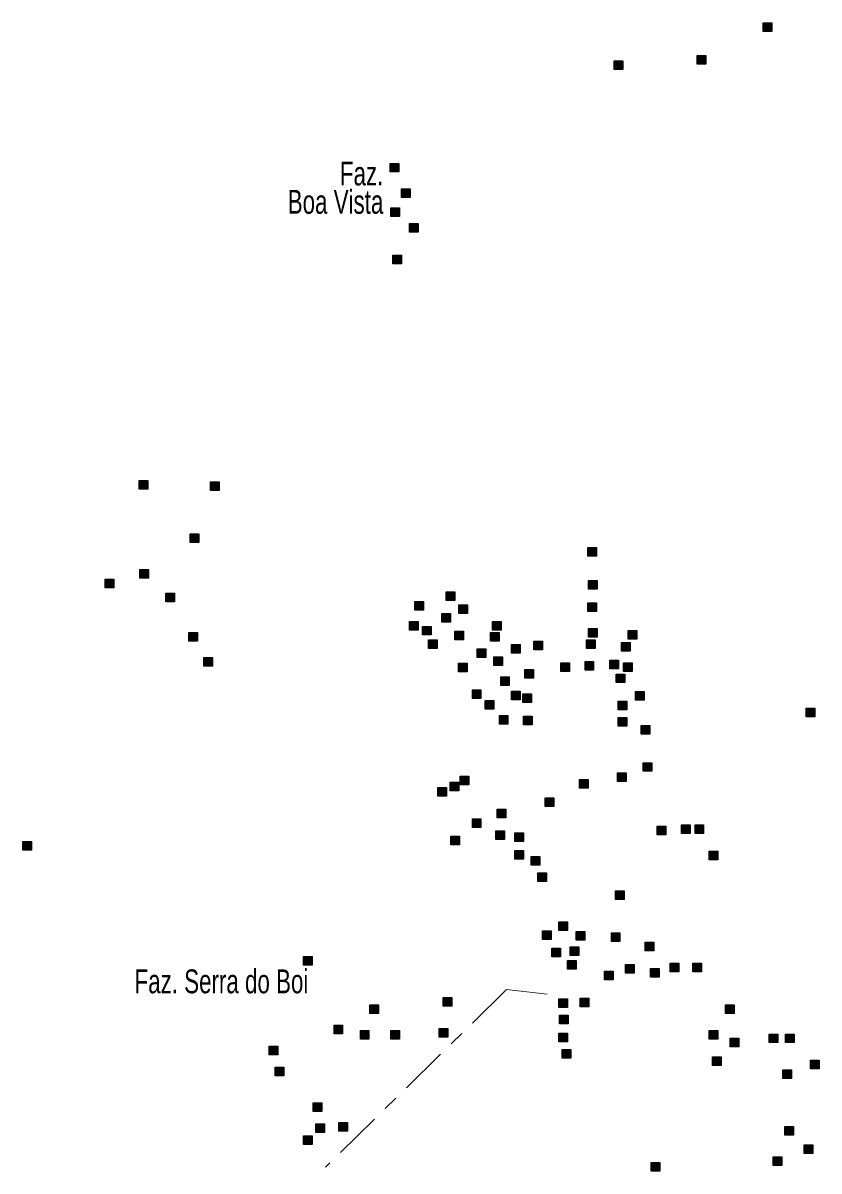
# Model space of a CAD drawing. Extents: x 445.4 to 500, y 8728.7 to 8784.
# Drawn here: x 457.46 to 462.8, y 8764.49 to 8772.19 of the extents above; entities that cross this region are included whole.
import ezdxf
from ezdxf.enums import TextEntityAlignment as Align

# ---------------------------------------------------------------- set-up
doc = ezdxf.new("R2010")
doc.units = 0
doc.header["$LTSCALE"] = 0.064
doc.linetypes.add('DOT_DASHED', pattern=[7.7, 5, -1.2, 0.3, -1.2])
doc.layers.add('2', color=7, linetype='Continuous', lineweight=25)
doc.layers.add('22', color=7, linetype='DOT_DASHED', lineweight=13)
doc.layers.add('61', color=7, linetype='Continuous')

msp = doc.modelspace()

# ---------------------------------------------------------------- hatches: boundary and pattern name
at = {"layer": '2'}
for points in [[(462.4248, 8772.1869), (462.4828, 8772.1869), (462.4828, 8772.1289), (462.4248, 8772.1289)], [(461.9814, 8771.9696), (462.0394, 8771.9696), (462.0394, 8771.9116), (461.9814, 8771.9116)], [(461.4248, 8771.9334), (461.4828, 8771.9334), (461.4828, 8771.8754), (461.4248, 8771.8754)], [(459.9225, 8771.2452), (459.9805, 8771.2452), (459.9805, 8771.1872), (459.9225, 8771.1872)], [(459.9994, 8771.0732), (460.0574, 8771.0732), (460.0574, 8771.0152), (459.9994, 8771.0152)], [(459.927, 8770.9464), (459.985, 8770.9464), (459.985, 8770.8884), (459.927, 8770.8884)], [(460.0537, 8770.8423), (460.1117, 8770.8423), (460.1117, 8770.7843), (460.0537, 8770.7843)], [(459.9406, 8770.6295), (459.9986, 8770.6295), (459.9986, 8770.5715), (459.9406, 8770.5715)], [(458.2392, 8769.1173), (458.2972, 8769.1173), (458.2972, 8769.0593), (458.2392, 8769.0593)], [(458.7188, 8769.1083), (458.7768, 8769.1083), (458.7768, 8769.0503), (458.7188, 8769.0503)], [(458.5831, 8768.7597), (458.6411, 8768.7597), (458.6411, 8768.7017), (458.5831, 8768.7017)], [(461.2483, 8768.6691), (461.3063, 8768.6691), (461.3063, 8768.6111), (461.2483, 8768.6111)], [(458.2437, 8768.5197), (458.3017, 8768.5197), (458.3017, 8768.4617), (458.2437, 8768.4617)], [(458.0129, 8768.4563), (458.0709, 8768.4563), (458.0709, 8768.3983), (458.0129, 8768.3983)], [(461.2529, 8768.4473), (461.3109, 8768.4473), (461.3109, 8768.3893), (461.2529, 8768.3893)], [(458.42, 8768.3613), (458.478, 8768.3613), (458.478, 8768.3033), (458.42, 8768.3033)], [(460.2981, 8768.3703), (460.3561, 8768.3703), (460.3561, 8768.3123), (460.2981, 8768.3123)], [(460.0899, 8768.3069), (460.1479, 8768.3069), (460.1479, 8768.2489), (460.0899, 8768.2489)], [(460.3841, 8768.2843), (460.4421, 8768.2843), (460.4421, 8768.2263), (460.3841, 8768.2263)], [(461.2483, 8768.2979), (461.3063, 8768.2979), (461.3063, 8768.2399), (461.2483, 8768.2399)], [(460.0537, 8768.1711), (460.1117, 8768.1711), (460.1117, 8768.1131), (460.0537, 8768.1131)], [(460.2709, 8768.2254), (460.3289, 8768.2254), (460.3289, 8768.1674), (460.2709, 8768.1674)], [(460.6103, 8768.1711), (460.6683, 8768.1711), (460.6683, 8768.1131), (460.6103, 8768.1131)], [(458.574, 8768.0987), (458.632, 8768.0987), (458.632, 8768.0407), (458.574, 8768.0407)], [(460.1397, 8768.1394), (460.1977, 8768.1394), (460.1977, 8768.0814), (460.1397, 8768.0814)], [(460.3569, 8768.1077), (460.4149, 8768.1077), (460.4149, 8768.0497), (460.3569, 8768.0497)], [(460.5967, 8768.0987), (460.6547, 8768.0987), (460.6547, 8768.0407), (460.5967, 8768.0407)], [(461.2529, 8768.1258), (461.3109, 8768.1258), (461.3109, 8768.0678), (461.2529, 8768.0678)], [(461.5198, 8768.1122), (461.5778, 8768.1122), (461.5778, 8768.0542), (461.5198, 8768.0542)], [(460.1804, 8768.0489), (460.2384, 8768.0489), (460.2384, 8767.9909), (460.1804, 8767.9909)], [(460.737, 8768.0172), (460.795, 8768.0172), (460.795, 8767.9592), (460.737, 8767.9592)], [(460.8863, 8768.0398), (460.9443, 8768.0398), (460.9443, 8767.9818), (460.8863, 8767.9818)], [(461.2393, 8768.0489), (461.2973, 8768.0489), (461.2973, 8767.9909), (461.2393, 8767.9909)], [(461.4746, 8768.0308), (461.5326, 8768.0308), (461.5326, 8767.9728), (461.4746, 8767.9728)], [(458.6736, 8767.9311), (458.7316, 8767.9311), (458.7316, 8767.8731), (458.6736, 8767.8731)], [(460.5062, 8767.989), (460.5642, 8767.989), (460.5642, 8767.931), (460.5062, 8767.931)], [(460.6194, 8767.9347), (460.6774, 8767.9347), (460.6774, 8767.8767), (460.6194, 8767.8767)], [(460.3824, 8767.8916), (460.4404, 8767.8916), (460.4404, 8767.8336), (460.3824, 8767.8336)], [(461.0673, 8767.8949), (461.1253, 8767.8949), (461.1253, 8767.8369), (461.0673, 8767.8369)], [(461.2302, 8767.904), (461.2882, 8767.904), (461.2882, 8767.846), (461.2302, 8767.846)], [(461.3977, 8767.913), (461.4557, 8767.913), (461.4557, 8767.855), (461.3977, 8767.855)], [(461.4882, 8767.8949), (461.5462, 8767.8949), (461.5462, 8767.8369), (461.4882, 8767.8369)], [(460.6646, 8767.7999), (460.7226, 8767.7999), (460.7226, 8767.7419), (460.6646, 8767.7419)], [(460.8275, 8767.8497), (460.8855, 8767.8497), (460.8855, 8767.7917), (460.8275, 8767.7917)], [(461.4384, 8767.8197), (461.4964, 8767.8197), (461.4964, 8767.7617), (461.4384, 8767.7617)], [(460.4746, 8767.7138), (460.5326, 8767.7138), (460.5326, 8767.6558), (460.4746, 8767.6558)], [(460.737, 8767.7048), (460.795, 8767.7048), (460.795, 8767.6468), (460.737, 8767.6468)], [(461.5696, 8767.702), (461.6276, 8767.702), (461.6276, 8767.644), (461.5696, 8767.644)], [(460.5605, 8767.6414), (460.6185, 8767.6414), (460.6185, 8767.5834), (460.5605, 8767.5834)], [(460.8139, 8767.6867), (460.8719, 8767.6867), (460.8719, 8767.6287), (460.8139, 8767.6287)], [(461.452, 8767.6369), (461.51, 8767.6369), (461.51, 8767.5789), (461.452, 8767.5789)], [(462.7139, 8767.5903), (462.7719, 8767.5903), (462.7719, 8767.5323), (462.7139, 8767.5323)], [(460.6556, 8767.5418), (460.7136, 8767.5418), (460.7136, 8767.4838), (460.6556, 8767.4838)], [(460.8185, 8767.5373), (460.8765, 8767.5373), (460.8765, 8767.4793), (460.8185, 8767.4793)], [(461.452, 8767.5282), (461.51, 8767.5282), (461.51, 8767.4702), (461.452, 8767.4702)], [(461.6058, 8767.4739), (461.6638, 8767.4739), (461.6638, 8767.4159), (461.6058, 8767.4159)], [(461.6194, 8767.2249), (461.6774, 8767.2249), (461.6774, 8767.1669), (461.6194, 8767.1669)], [(460.3252, 8767.0936), (460.3832, 8767.0936), (460.3832, 8767.0356), (460.3252, 8767.0356)], [(460.3931, 8767.1343), (460.4511, 8767.1343), (460.4511, 8767.0763), (460.3931, 8767.0763)], [(461.194, 8767.1117), (461.252, 8767.1117), (461.252, 8767.0537), (461.194, 8767.0537)], [(461.4474, 8767.157), (461.5054, 8767.157), (461.5054, 8767.099), (461.4474, 8767.099)], [(460.2438, 8767.0574), (460.3018, 8767.0574), (460.3018, 8766.9994), (460.2438, 8766.9994)], [(460.9633, 8766.9894), (461.0213, 8766.9894), (461.0213, 8766.9314), (460.9633, 8766.9314)], [(460.642, 8766.9125), (460.7, 8766.9125), (460.7, 8766.8545), (460.642, 8766.8545)], [(460.4746, 8766.8491), (460.5326, 8766.8491), (460.5326, 8766.7911), (460.4746, 8766.7911)], [(461.7144, 8766.7993), (461.7724, 8766.7993), (461.7724, 8766.7413), (461.7144, 8766.7413)], [(461.8773, 8766.8083), (461.9353, 8766.8083), (461.9353, 8766.7503), (461.8773, 8766.7503)], [(461.9678, 8766.8083), (462.0258, 8766.8083), (462.0258, 8766.7503), (461.9678, 8766.7503)], [(460.3298, 8766.7314), (460.3878, 8766.7314), (460.3878, 8766.6734), (460.3298, 8766.6734)], [(460.6329, 8766.7676), (460.6909, 8766.7676), (460.6909, 8766.7096), (460.6329, 8766.7096)], [(460.7596, 8766.754), (460.8176, 8766.754), (460.8176, 8766.696), (460.7596, 8766.696)], [(457.4609, 8766.6952), (457.5189, 8766.6952), (457.5189, 8766.6372), (457.4609, 8766.6372)], [(460.7596, 8766.6363), (460.8176, 8766.6363), (460.8176, 8766.5783), (460.7596, 8766.5783)], [(462.0628, 8766.6318), (462.1208, 8766.6318), (462.1208, 8766.5738), (462.0628, 8766.5738)], [(460.8682, 8766.5956), (460.9262, 8766.5956), (460.9262, 8766.5376), (460.8682, 8766.5376)], [(460.9135, 8766.4869), (460.9715, 8766.4869), (460.9715, 8766.4289), (460.9135, 8766.4289)], [(461.4339, 8766.3647), (461.4919, 8766.3647), (461.4919, 8766.3067), (461.4339, 8766.3067)], [(460.9452, 8766.0975), (461.0032, 8766.0975), (461.0032, 8766.0395), (460.9452, 8766.0395)], [(461.0538, 8766.1564), (461.1118, 8766.1564), (461.1118, 8766.0984), (461.0538, 8766.0984)], [(461.1714, 8766.093), (461.2294, 8766.093), (461.2294, 8766.035), (461.1714, 8766.035)], [(461.4067, 8766.084), (461.4647, 8766.084), (461.4647, 8766.026), (461.4067, 8766.026)], [(461.633, 8766.0206), (461.691, 8766.0206), (461.691, 8765.9626), (461.633, 8765.9626)], [(461.0085, 8765.9798), (461.0665, 8765.9798), (461.0665, 8765.9218), (461.0085, 8765.9218)], [(461.1307, 8765.9889), (461.1887, 8765.9889), (461.1887, 8765.9309), (461.1307, 8765.9309)], [(459.3433, 8765.9255), (459.4013, 8765.9255), (459.4013, 8765.8675), (459.3433, 8765.8675)], [(461.1126, 8765.8983), (461.1706, 8765.8983), (461.1706, 8765.8403), (461.1126, 8765.8403)], [(461.5017, 8765.8712), (461.5597, 8765.8712), (461.5597, 8765.8132), (461.5017, 8765.8132)], [(461.8004, 8765.8802), (461.8584, 8765.8802), (461.8584, 8765.8222), (461.8004, 8765.8222)], [(461.9542, 8765.8802), (462.0122, 8765.8802), (462.0122, 8765.8222), (461.9542, 8765.8222)], [(461.3615, 8765.8259), (461.4195, 8765.8259), (461.4195, 8765.7679), (461.3615, 8765.7679)], [(461.6692, 8765.844), (461.7272, 8765.844), (461.7272, 8765.786), (461.6692, 8765.786)], [(460.28, 8765.6493), (460.338, 8765.6493), (460.338, 8765.5913), (460.28, 8765.5913)], [(461.0538, 8765.6403), (461.1118, 8765.6403), (461.1118, 8765.5823), (461.0538, 8765.5823)], [(461.1986, 8765.6448), (461.2566, 8765.6448), (461.2566, 8765.5868), (461.1986, 8765.5868)], [(459.7867, 8765.5995), (459.8447, 8765.5995), (459.8447, 8765.5415), (459.7867, 8765.5415)], [(462.1714, 8765.5995), (462.2294, 8765.5995), (462.2294, 8765.5415), (462.1714, 8765.5415)], [(461.0583, 8765.5316), (461.1163, 8765.5316), (461.1163, 8765.4736), (461.0583, 8765.4736)], [(459.5469, 8765.4637), (459.6049, 8765.4637), (459.6049, 8765.4057), (459.5469, 8765.4057)], [(459.7234, 8765.4275), (459.7814, 8765.4275), (459.7814, 8765.3695), (459.7234, 8765.3695)], [(459.927, 8765.4275), (459.985, 8765.4275), (459.985, 8765.3695), (459.927, 8765.3695)], [(460.2528, 8765.4411), (460.3108, 8765.4411), (460.3108, 8765.3831), (460.2528, 8765.3831)], [(461.0538, 8765.4094), (461.1118, 8765.4094), (461.1118, 8765.3514), (461.0538, 8765.3514)], [(462.0628, 8765.4275), (462.1208, 8765.4275), (462.1208, 8765.3695), (462.0628, 8765.3695)], [(462.4656, 8765.4048), (462.5236, 8765.4048), (462.5236, 8765.3468), (462.4656, 8765.3468)], [(462.5742, 8765.4048), (462.6322, 8765.4048), (462.6322, 8765.3468), (462.5742, 8765.3468)], [(459.1125, 8765.3233), (459.1705, 8765.3233), (459.1705, 8765.2653), (459.1125, 8765.2653)], [(462.2031, 8765.3777), (462.2611, 8765.3777), (462.2611, 8765.3197), (462.2031, 8765.3197)], [(461.0764, 8765.3007), (461.1344, 8765.3007), (461.1344, 8765.2427), (461.0764, 8765.2427)], [(462.0855, 8765.2509), (462.1435, 8765.2509), (462.1435, 8765.1929), (462.0855, 8765.1929)], [(459.1532, 8765.183), (459.2112, 8765.183), (459.2112, 8765.125), (459.1532, 8765.125)], [(462.5561, 8765.1649), (462.6141, 8765.1649), (462.6141, 8765.1069), (462.5561, 8765.1069)], [(462.7416, 8765.2283), (462.7996, 8765.2283), (462.7996, 8765.1703), (462.7416, 8765.1703)], [(459.4066, 8764.943), (459.4646, 8764.943), (459.4646, 8764.885), (459.4066, 8764.885)], [(459.4247, 8764.8027), (459.4827, 8764.8027), (459.4827, 8764.7447), (459.4247, 8764.7447)], [(459.5786, 8764.8117), (459.6366, 8764.8117), (459.6366, 8764.7537), (459.5786, 8764.7537)], [(462.5696, 8764.7846), (462.6276, 8764.7846), (462.6276, 8764.7266), (462.5696, 8764.7266)], [(459.3433, 8764.7212), (459.4013, 8764.7212), (459.4013, 8764.6632), (459.3433, 8764.6632)], [(462.7009, 8764.6613), (462.7589, 8764.6613), (462.7589, 8764.6033), (462.7009, 8764.6033)], [(461.6737, 8764.5436), (461.7317, 8764.5436), (461.7317, 8764.4856), (461.6737, 8764.4856)], [(462.4927, 8764.5799), (462.5507, 8764.5799), (462.5507, 8764.5219), (462.4927, 8764.5219)]]:
    msp.add_hatch(color=256, dxfattribs=at).paths.add_polyline_path(points)

# ---------------------------------------------------------------- linework, layer by layer
for points in [[(462.4248, 8772.1869), (462.4828, 8772.1869), (462.4828, 8772.1289), (462.4248, 8772.1289)], [(461.9814, 8771.9696), (462.0394, 8771.9696), (462.0394, 8771.9116), (461.9814, 8771.9116)], [(461.4248, 8771.9334), (461.4828, 8771.9334), (461.4828, 8771.8754), (461.4248, 8771.8754)], [(459.9225, 8771.2452), (459.9805, 8771.2452), (459.9805, 8771.1872), (459.9225, 8771.1872)], [(459.9994, 8771.0732), (460.0574, 8771.0732), (460.0574, 8771.0152), (459.9994, 8771.0152)], [(459.927, 8770.9464), (459.985, 8770.9464), (459.985, 8770.8884), (459.927, 8770.8884)], [(460.0537, 8770.8423), (460.1117, 8770.8423), (460.1117, 8770.7843), (460.0537, 8770.7843)], [(459.9406, 8770.6295), (459.9986, 8770.6295), (459.9986, 8770.5715), (459.9406, 8770.5715)], [(458.2392, 8769.1173), (458.2972, 8769.1173), (458.2972, 8769.0593), (458.2392, 8769.0593)], [(458.7188, 8769.1083), (458.7768, 8769.1083), (458.7768, 8769.0503), (458.7188, 8769.0503)], [(458.5831, 8768.7597), (458.6411, 8768.7597), (458.6411, 8768.7017), (458.5831, 8768.7017)], [(461.2483, 8768.6691), (461.3063, 8768.6691), (461.3063, 8768.6111), (461.2483, 8768.6111)], [(458.2437, 8768.5197), (458.3017, 8768.5197), (458.3017, 8768.4617), (458.2437, 8768.4617)], [(458.0129, 8768.4563), (458.0709, 8768.4563), (458.0709, 8768.3983), (458.0129, 8768.3983)], [(461.2529, 8768.4473), (461.3109, 8768.4473), (461.3109, 8768.3893), (461.2529, 8768.3893)], [(458.42, 8768.3613), (458.478, 8768.3613), (458.478, 8768.3033), (458.42, 8768.3033)], [(460.2981, 8768.3703), (460.3561, 8768.3703), (460.3561, 8768.3123), (460.2981, 8768.3123)], [(460.0899, 8768.3069), (460.1479, 8768.3069), (460.1479, 8768.2489), (460.0899, 8768.2489)], [(460.3841, 8768.2843), (460.4421, 8768.2843), (460.4421, 8768.2263), (460.3841, 8768.2263)], [(461.2483, 8768.2979), (461.3063, 8768.2979), (461.3063, 8768.2399), (461.2483, 8768.2399)], [(460.0537, 8768.1711), (460.1117, 8768.1711), (460.1117, 8768.1131), (460.0537, 8768.1131)], [(460.2709, 8768.2254), (460.3289, 8768.2254), (460.3289, 8768.1674), (460.2709, 8768.1674)], [(460.6103, 8768.1711), (460.6683, 8768.1711), (460.6683, 8768.1131), (460.6103, 8768.1131)], [(458.574, 8768.0987), (458.632, 8768.0987), (458.632, 8768.0407), (458.574, 8768.0407)], [(460.1397, 8768.1394), (460.1977, 8768.1394), (460.1977, 8768.0814), (460.1397, 8768.0814)], [(460.3569, 8768.1077), (460.4149, 8768.1077), (460.4149, 8768.0497), (460.3569, 8768.0497)], [(460.5967, 8768.0987), (460.6547, 8768.0987), (460.6547, 8768.0407), (460.5967, 8768.0407)], [(461.2529, 8768.1258), (461.3109, 8768.1258), (461.3109, 8768.0678), (461.2529, 8768.0678)], [(461.5198, 8768.1122), (461.5778, 8768.1122), (461.5778, 8768.0542), (461.5198, 8768.0542)], [(460.1804, 8768.0489), (460.2384, 8768.0489), (460.2384, 8767.9909), (460.1804, 8767.9909)], [(460.737, 8768.0172), (460.795, 8768.0172), (460.795, 8767.9592), (460.737, 8767.9592)], [(460.8863, 8768.0398), (460.9443, 8768.0398), (460.9443, 8767.9818), (460.8863, 8767.9818)], [(461.2393, 8768.0489), (461.2973, 8768.0489), (461.2973, 8767.9909), (461.2393, 8767.9909)], [(461.4746, 8768.0308), (461.5326, 8768.0308), (461.5326, 8767.9728), (461.4746, 8767.9728)], [(458.6736, 8767.9311), (458.7316, 8767.9311), (458.7316, 8767.8731), (458.6736, 8767.8731)], [(460.5062, 8767.989), (460.5642, 8767.989), (460.5642, 8767.931), (460.5062, 8767.931)], [(460.6194, 8767.9347), (460.6774, 8767.9347), (460.6774, 8767.8767), (460.6194, 8767.8767)], [(460.3824, 8767.8916), (460.4404, 8767.8916), (460.4404, 8767.8336), (460.3824, 8767.8336)], [(461.0673, 8767.8949), (461.1253, 8767.8949), (461.1253, 8767.8369), (461.0673, 8767.8369)], [(461.2302, 8767.904), (461.2882, 8767.904), (461.2882, 8767.846), (461.2302, 8767.846)], [(461.3977, 8767.913), (461.4557, 8767.913), (461.4557, 8767.855), (461.3977, 8767.855)], [(461.4882, 8767.8949), (461.5462, 8767.8949), (461.5462, 8767.8369), (461.4882, 8767.8369)], [(460.6646, 8767.7999), (460.7226, 8767.7999), (460.7226, 8767.7419), (460.6646, 8767.7419)], [(460.8275, 8767.8497), (460.8855, 8767.8497), (460.8855, 8767.7917), (460.8275, 8767.7917)], [(461.4384, 8767.8197), (461.4964, 8767.8197), (461.4964, 8767.7617), (461.4384, 8767.7617)], [(460.4746, 8767.7138), (460.5326, 8767.7138), (460.5326, 8767.6558), (460.4746, 8767.6558)], [(460.737, 8767.7048), (460.795, 8767.7048), (460.795, 8767.6468), (460.737, 8767.6468)], [(461.5696, 8767.702), (461.6276, 8767.702), (461.6276, 8767.644), (461.5696, 8767.644)], [(460.5605, 8767.6414), (460.6185, 8767.6414), (460.6185, 8767.5834), (460.5605, 8767.5834)], [(460.8139, 8767.6867), (460.8719, 8767.6867), (460.8719, 8767.6287), (460.8139, 8767.6287)], [(461.452, 8767.6369), (461.51, 8767.6369), (461.51, 8767.5789), (461.452, 8767.5789)], [(462.7139, 8767.5903), (462.7719, 8767.5903), (462.7719, 8767.5323), (462.7139, 8767.5323)], [(460.6556, 8767.5418), (460.7136, 8767.5418), (460.7136, 8767.4838), (460.6556, 8767.4838)], [(460.8185, 8767.5373), (460.8765, 8767.5373), (460.8765, 8767.4793), (460.8185, 8767.4793)], [(461.452, 8767.5282), (461.51, 8767.5282), (461.51, 8767.4702), (461.452, 8767.4702)], [(461.6058, 8767.4739), (461.6638, 8767.4739), (461.6638, 8767.4159), (461.6058, 8767.4159)], [(461.6194, 8767.2249), (461.6774, 8767.2249), (461.6774, 8767.1669), (461.6194, 8767.1669)], [(460.3252, 8767.0936), (460.3832, 8767.0936), (460.3832, 8767.0356), (460.3252, 8767.0356)], [(460.3931, 8767.1343), (460.4511, 8767.1343), (460.4511, 8767.0763), (460.3931, 8767.0763)], [(461.194, 8767.1117), (461.252, 8767.1117), (461.252, 8767.0537), (461.194, 8767.0537)], [(461.4474, 8767.157), (461.5054, 8767.157), (461.5054, 8767.099), (461.4474, 8767.099)], [(460.2438, 8767.0574), (460.3018, 8767.0574), (460.3018, 8766.9994), (460.2438, 8766.9994)], [(460.9633, 8766.9894), (461.0213, 8766.9894), (461.0213, 8766.9314), (460.9633, 8766.9314)], [(460.642, 8766.9125), (460.7, 8766.9125), (460.7, 8766.8545), (460.642, 8766.8545)], [(460.4746, 8766.8491), (460.5326, 8766.8491), (460.5326, 8766.7911), (460.4746, 8766.7911)], [(461.7144, 8766.7993), (461.7724, 8766.7993), (461.7724, 8766.7413), (461.7144, 8766.7413)], [(461.8773, 8766.8083), (461.9353, 8766.8083), (461.9353, 8766.7503), (461.8773, 8766.7503)], [(461.9678, 8766.8083), (462.0258, 8766.8083), (462.0258, 8766.7503), (461.9678, 8766.7503)], [(460.3298, 8766.7314), (460.3878, 8766.7314), (460.3878, 8766.6734), (460.3298, 8766.6734)], [(460.6329, 8766.7676), (460.6909, 8766.7676), (460.6909, 8766.7096), (460.6329, 8766.7096)], [(460.7596, 8766.754), (460.8176, 8766.754), (460.8176, 8766.696), (460.7596, 8766.696)], [(457.4609, 8766.6952), (457.5189, 8766.6952), (457.5189, 8766.6372), (457.4609, 8766.6372)], [(460.7596, 8766.6363), (460.8176, 8766.6363), (460.8176, 8766.5783), (460.7596, 8766.5783)], [(462.0628, 8766.6318), (462.1208, 8766.6318), (462.1208, 8766.5738), (462.0628, 8766.5738)], [(460.8682, 8766.5956), (460.9262, 8766.5956), (460.9262, 8766.5376), (460.8682, 8766.5376)], [(460.9135, 8766.4869), (460.9715, 8766.4869), (460.9715, 8766.4289), (460.9135, 8766.4289)], [(461.4339, 8766.3647), (461.4919, 8766.3647), (461.4919, 8766.3067), (461.4339, 8766.3067)], [(460.9452, 8766.0975), (461.0032, 8766.0975), (461.0032, 8766.0395), (460.9452, 8766.0395)], [(461.0538, 8766.1564), (461.1118, 8766.1564), (461.1118, 8766.0984), (461.0538, 8766.0984)], [(461.1714, 8766.093), (461.2294, 8766.093), (461.2294, 8766.035), (461.1714, 8766.035)], [(461.4067, 8766.084), (461.4647, 8766.084), (461.4647, 8766.026), (461.4067, 8766.026)], [(461.633, 8766.0206), (461.691, 8766.0206), (461.691, 8765.9626), (461.633, 8765.9626)], [(461.0085, 8765.9798), (461.0665, 8765.9798), (461.0665, 8765.9218), (461.0085, 8765.9218)], [(461.1307, 8765.9889), (461.1887, 8765.9889), (461.1887, 8765.9309), (461.1307, 8765.9309)], [(459.3433, 8765.9255), (459.4013, 8765.9255), (459.4013, 8765.8675), (459.3433, 8765.8675)], [(461.1126, 8765.8983), (461.1706, 8765.8983), (461.1706, 8765.8403), (461.1126, 8765.8403)], [(461.5017, 8765.8712), (461.5597, 8765.8712), (461.5597, 8765.8132), (461.5017, 8765.8132)], [(461.8004, 8765.8802), (461.8584, 8765.8802), (461.8584, 8765.8222), (461.8004, 8765.8222)], [(461.9542, 8765.8802), (462.0122, 8765.8802), (462.0122, 8765.8222), (461.9542, 8765.8222)], [(461.3615, 8765.8259), (461.4195, 8765.8259), (461.4195, 8765.7679), (461.3615, 8765.7679)], [(461.6692, 8765.844), (461.7272, 8765.844), (461.7272, 8765.786), (461.6692, 8765.786)], [(460.28, 8765.6493), (460.338, 8765.6493), (460.338, 8765.5913), (460.28, 8765.5913)], [(461.0538, 8765.6403), (461.1118, 8765.6403), (461.1118, 8765.5823), (461.0538, 8765.5823)], [(461.1986, 8765.6448), (461.2566, 8765.6448), (461.2566, 8765.5868), (461.1986, 8765.5868)], [(459.7867, 8765.5995), (459.8447, 8765.5995), (459.8447, 8765.5415), (459.7867, 8765.5415)], [(462.1714, 8765.5995), (462.2294, 8765.5995), (462.2294, 8765.5415), (462.1714, 8765.5415)], [(461.0583, 8765.5316), (461.1163, 8765.5316), (461.1163, 8765.4736), (461.0583, 8765.4736)], [(459.5469, 8765.4637), (459.6049, 8765.4637), (459.6049, 8765.4057), (459.5469, 8765.4057)], [(459.7234, 8765.4275), (459.7814, 8765.4275), (459.7814, 8765.3695), (459.7234, 8765.3695)], [(459.927, 8765.4275), (459.985, 8765.4275), (459.985, 8765.3695), (459.927, 8765.3695)], [(460.2528, 8765.4411), (460.3108, 8765.4411), (460.3108, 8765.3831), (460.2528, 8765.3831)], [(461.0538, 8765.4094), (461.1118, 8765.4094), (461.1118, 8765.3514), (461.0538, 8765.3514)], [(462.0628, 8765.4275), (462.1208, 8765.4275), (462.1208, 8765.3695), (462.0628, 8765.3695)], [(462.4656, 8765.4048), (462.5236, 8765.4048), (462.5236, 8765.3468), (462.4656, 8765.3468)], [(462.5742, 8765.4048), (462.6322, 8765.4048), (462.6322, 8765.3468), (462.5742, 8765.3468)], [(459.1125, 8765.3233), (459.1705, 8765.3233), (459.1705, 8765.2653), (459.1125, 8765.2653)], [(462.2031, 8765.3777), (462.2611, 8765.3777), (462.2611, 8765.3197), (462.2031, 8765.3197)], [(461.0764, 8765.3007), (461.1344, 8765.3007), (461.1344, 8765.2427), (461.0764, 8765.2427)], [(462.0855, 8765.2509), (462.1435, 8765.2509), (462.1435, 8765.1929), (462.0855, 8765.1929)], [(459.1532, 8765.183), (459.2112, 8765.183), (459.2112, 8765.125), (459.1532, 8765.125)], [(462.5561, 8765.1649), (462.6141, 8765.1649), (462.6141, 8765.1069), (462.5561, 8765.1069)], [(462.7416, 8765.2283), (462.7996, 8765.2283), (462.7996, 8765.1703), (462.7416, 8765.1703)], [(459.4066, 8764.943), (459.4646, 8764.943), (459.4646, 8764.885), (459.4066, 8764.885)], [(459.4247, 8764.8027), (459.4827, 8764.8027), (459.4827, 8764.7447), (459.4247, 8764.7447)], [(459.5786, 8764.8117), (459.6366, 8764.8117), (459.6366, 8764.7537), (459.5786, 8764.7537)], [(462.5696, 8764.7846), (462.6276, 8764.7846), (462.6276, 8764.7266), (462.5696, 8764.7266)], [(459.3433, 8764.7212), (459.4013, 8764.7212), (459.4013, 8764.6632), (459.3433, 8764.6632)], [(462.7009, 8764.6613), (462.7589, 8764.6613), (462.7589, 8764.6033), (462.7009, 8764.6033)], [(461.6737, 8764.5436), (461.7317, 8764.5436), (461.7317, 8764.4856), (461.6737, 8764.4856)], [(462.4927, 8764.5799), (462.5507, 8764.5799), (462.5507, 8764.5219), (462.4927, 8764.5219)]]:
    msp.add_lwpolyline(points, close=True, dxfattribs=at)
at = {"layer": '22'}
msp.add_lwpolyline([(460.9767, 8765.671), (460.7034, 8765.7027), (459.4888, 8764.5112)], dxfattribs=at)

# ---------------------------------------------------------------- texts
at = {"layer": '61', "width": 0.7}
for s, p in [('         Faz.', (459.8776, 8771.0971)), ('Boa Vista', (459.8776, 8770.9071))]:
    msp.add_text(s, height=0.16, dxfattribs=at).set_placement(p, align=Align.RIGHT)
msp.add_text('Faz. Serra do Boi', height=0.16, dxfattribs=at).set_placement((458.2093, 8765.678))

doc.saveas('drawing.dxf')
